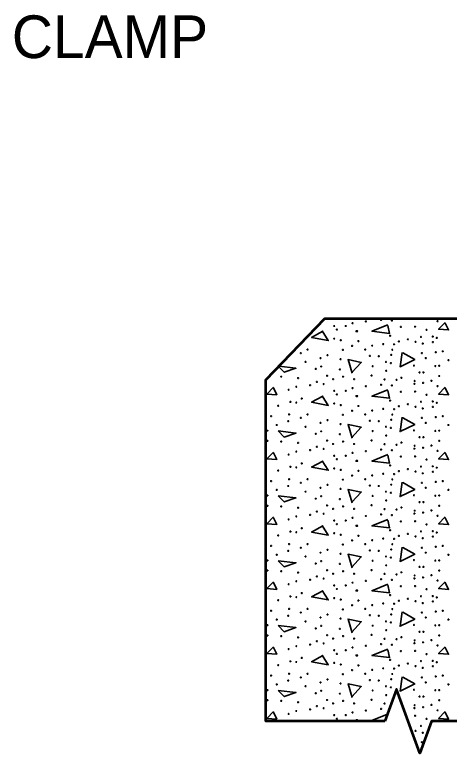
# Model space of a CAD drawing. Extents: x -105 to 751, y -65 to 479.
# Drawn here: x 328.8 to 359.4, y 310.5 to 362.5 of the extents above; entities that cross this region are included whole.
import ezdxf

# ---------------------------------------------------------------- set-up
doc = ezdxf.new("R2010")
doc.units = 0
doc.header["$LTSCALE"] = 1.2
doc.layers.add('1', color=7, linetype='Continuous', lineweight=35)

msp = doc.modelspace()

# ---------------------------------------------------------------- linework, layer by layer
at = {"layer": '1'}
for p, q in [((350.532, 312.839), (350.434, 312.786)), ((350.533, 312.786), (350.484, 312.863))]:
    msp.add_line(p, q, dxfattribs=at)
at = {"layer": '1', "lineweight": 53}
msp.add_lwpolyline([(354.913, 312.786), (346.512, 312.786), (346.512, 336.786), (350.68, 341.102), (385.481, 341.102), (389.649, 336.786), (389.649, 312.786), (381.249, 312.786), (380.428, 310.531), (378.786, 315.041), (377.965, 312.786), (358.196, 312.786), (357.375, 310.531), (355.733, 315.041)], close=True, dxfattribs=at)
at = {"layer": '1'}
for points in [[(355.116, 340.655), (353.988, 340.199), (355.236, 340.055), (355.116, 340.607)], [(359.148, 340.823), (358.692, 340.343), (359.388, 340.295), (359.148, 340.775)], [(350.532, 340.199), (349.74, 339.767), (350.916, 339.551), (350.484, 340.223)], [(356.172, 338.687), (357.012, 338.207), (355.98, 337.703), (356.124, 338.711)], [(352.596, 337.247), (352.308, 338.207), (353.244, 338.015), (352.572, 337.295)], [(347.439, 337.745), (348.636, 337.607), (347.82, 337.319), (347.417, 337.722)], [(347.052, 336.263), (346.596, 335.783), (347.292, 335.735), (347.052, 336.215)], [(355.116, 336.095), (353.988, 335.639), (355.236, 335.495), (355.116, 336.047)], [(359.148, 336.263), (358.692, 335.783), (359.388, 335.735), (359.148, 336.215)], [(350.532, 335.639), (349.74, 335.207), (350.916, 334.991), (350.484, 335.663)], [(356.172, 334.127), (357.012, 333.647), (355.98, 333.143), (356.124, 334.151)], [(352.596, 332.687), (352.308, 333.647), (353.244, 333.455), (352.572, 332.735)], [(347.052, 331.703), (346.596, 331.223), (347.292, 331.175), (347.052, 331.655)], [(355.116, 331.535), (353.988, 331.079), (355.236, 330.935), (355.116, 331.487)], [(359.148, 331.703), (358.692, 331.223), (359.388, 331.175), (359.148, 331.655)], [(350.532, 331.079), (349.74, 330.647), (350.916, 330.431), (350.484, 331.103)], [(356.172, 329.567), (357.012, 329.087), (355.98, 328.583), (356.124, 329.591)], [(352.596, 328.127), (352.308, 329.087), (353.244, 328.895), (352.572, 328.175)], [(347.052, 327.143), (346.596, 326.663), (347.292, 326.615), (347.052, 327.095)], [(355.116, 326.975), (353.988, 326.519), (355.236, 326.375), (355.116, 326.927)], [(359.148, 327.143), (358.692, 326.663), (359.388, 326.615), (359.148, 327.095)], [(350.532, 326.519), (349.74, 326.087), (350.916, 325.871), (350.484, 326.543)], [(356.172, 325.007), (357.012, 324.527), (355.98, 324.023), (356.124, 325.031)], [(352.596, 323.567), (352.308, 324.527), (353.244, 324.335), (352.572, 323.615)], [(347.052, 322.583), (346.596, 322.103), (347.292, 322.055), (347.052, 322.535)], [(359.148, 322.583), (358.692, 322.103), (359.388, 322.055), (359.148, 322.535)], [(350.532, 321.959), (349.74, 321.527), (350.916, 321.311), (350.484, 321.983)], [(355.116, 322.415), (353.988, 321.959), (355.236, 321.815), (355.116, 322.367)], [(356.172, 320.447), (357.012, 319.967), (355.98, 319.463), (356.124, 320.471)], [(352.596, 319.007), (352.308, 319.967), (353.244, 319.775), (352.572, 319.055)], [(347.052, 318.023), (346.596, 317.543), (347.292, 317.495), (347.052, 317.975)], [(355.116, 317.855), (353.988, 317.399), (355.236, 317.255), (355.116, 317.807)], [(359.148, 318.023), (358.692, 317.543), (359.388, 317.495), (359.148, 317.975)], [(350.532, 317.399), (349.74, 316.967), (350.916, 316.751), (350.484, 317.423)], [(356.172, 315.887), (357.012, 315.407), (355.98, 314.903), (356.124, 315.911)], [(352.596, 314.447), (352.308, 315.407), (353.244, 315.215), (352.572, 314.495)], [(347.052, 313.463), (346.596, 312.983), (347.292, 312.935), (347.052, 313.415)], [(355.095, 313.287), (353.988, 312.839), (354.45, 312.786)], [(359.148, 313.463), (358.692, 312.983), (359.388, 312.935), (359.148, 313.415)]]:
    msp.add_lwpolyline(points, dxfattribs=at)
for points in [[(347.388, 333.191), (348.636, 333.047), (347.82, 332.759)], [(347.388, 328.631), (348.636, 328.487), (347.82, 328.199)], [(347.388, 324.071), (348.636, 323.927), (347.82, 323.639)], [(347.388, 319.511), (348.636, 319.367), (347.82, 319.079)], [(347.388, 314.951), (348.636, 314.807), (347.82, 314.519)]]:
    msp.add_lwpolyline(points, close=True, dxfattribs=at)
for centre in [(352.629, 340.765), (353.568, 340.892), (354.633, 341.003), (355.397, 340.955), (356.987, 341.067), (358.618, 340.908), (351.341, 340.574), (351.532, 340.319), (352.152, 340.574), (352.9, 340.208), (352.963, 340.208), (356.033, 340.51), (357.035, 340.526), (357.846, 340.303), (351.341, 339.683), (355.269, 339.89), (356.526, 339.635), (357.448, 339.81), (358.275, 339.826), (358.555, 339.731), (351.802, 339.571), (352.598, 339.174), (353.043, 339.508), (354.013, 339.19), (354.792, 339.301), (355.556, 339.285), (355.89, 339.492), (357.067, 339.46), (357.576, 339.333), (358.291, 339.444), (348.987, 338.665), (349.465, 338.919), (351.946, 338.887), (353.52, 338.919), (355.349, 338.537), (355.429, 338.903), (357.512, 338.665), (358.482, 338.728), (358.984, 338.792), (349.321, 338.044), (350.371, 338.315), (350.864, 338.521), (351.787, 338.235), (353.854, 338.474), (354.474, 338.442), (354.983, 338.044), (357.782, 338.315), (359.382, 338.171), (350.037, 337.551), (350.419, 337.726), (351.739, 337.519), (354.045, 337.742), (355.333, 337.965), (356.955, 337.79), (358.458, 337.755), (358.73, 337.774), (347.604, 337.01), (350.832, 337.074), (351.961, 337.01), (353.965, 337.09), (354.999, 337.424), (357.353, 337.312), (357.623, 337.312), (358.73, 337.058), (348.797, 336.915), (350.117, 336.644), (350.594, 336.491), (351.262, 336.835), (352.741, 336.835), (354.888, 336.819), (355.731, 336.787), (356.065, 336.931), (356.987, 336.507), (357.003, 336.708), (357.591, 336.57), (358.18, 336.724), (348.129, 336.093), (348.669, 336.3), (349.64, 336.411), (351.341, 336.014), (352.152, 336.014), (352.629, 336.205), (353.568, 336.332), (354.633, 336.443), (355.397, 336.395), (356.033, 335.95), (357.035, 335.966), (358.618, 336.348), (349.051, 335.473), (351.532, 335.759), (352.9, 335.648), (352.963, 335.648), (357.846, 335.743), (347.397, 334.964), (348.256, 335.234), (348.669, 335.186), (351.341, 335.123), (351.802, 335.011), (353.043, 334.948), (355.269, 335.33), (355.89, 334.932), (356.526, 335.075), (357.448, 335.25), (358.275, 335.266), (358.555, 335.171), (352.598, 334.614), (354.013, 334.63), (354.792, 334.741), (355.556, 334.725), (357.067, 334.9), (357.576, 334.773), (358.291, 334.884), (346.888, 334.232), (348.097, 333.882), (348.16, 334.359), (348.987, 334.105), (349.465, 334.359), (350.864, 333.961), (351.946, 334.327), (353.52, 334.359), (353.854, 333.914), (354.474, 333.882), (355.349, 333.977), (355.429, 334.343), (357.512, 334.105), (358.482, 334.168), (358.984, 334.232), (347.286, 333.611), (349.321, 333.484), (350.371, 333.755), (351.787, 333.675), (354.983, 333.484), (355.333, 333.405), (357.782, 333.755), (359.382, 333.611), (346.634, 333.214), (350.037, 332.991), (350.419, 333.166), (351.739, 332.959), (354.045, 333.182), (354.999, 332.864), (356.955, 333.23), (358.458, 333.195), (358.73, 333.214), (346.634, 332.498), (347.604, 332.45), (348.797, 332.355), (350.832, 332.514), (351.961, 332.45), (353.965, 332.53), (356.065, 332.371), (357.353, 332.752), (357.623, 332.752), (358.73, 332.498), (349.64, 331.851), (350.117, 332.084), (350.594, 331.931), (351.262, 332.275), (352.741, 332.275), (354.633, 331.883), (354.888, 332.259), (355.397, 331.835), (355.731, 332.227), (356.987, 331.947), (357.003, 332.148), (357.591, 332.01), (358.18, 332.164), (358.618, 331.788), (348.129, 331.533), (348.669, 331.74), (351.341, 331.454), (352.152, 331.454), (352.629, 331.645), (353.568, 331.772), (356.033, 331.39), (357.035, 331.406), (349.051, 330.913), (351.532, 331.199), (352.9, 331.088), (352.963, 331.088), (355.269, 330.77), (357.846, 331.183), (347.397, 330.404), (348.256, 330.674), (348.669, 330.626), (351.341, 330.563), (351.802, 330.451), (353.043, 330.388), (355.89, 330.372), (356.526, 330.515), (357.067, 330.34), (357.448, 330.69), (358.275, 330.706), (358.291, 330.324), (358.555, 330.611), (348.16, 329.799), (349.465, 329.799), (351.946, 329.767), (352.598, 330.054), (353.52, 329.799), (354.013, 330.07), (354.792, 330.181), (355.429, 329.783), (355.556, 330.165), (357.576, 330.213), (346.888, 329.672), (348.097, 329.322), (348.987, 329.545), (350.371, 329.195), (350.864, 329.401), (353.854, 329.354), (354.474, 329.322), (355.349, 329.417), (357.512, 329.545), (357.782, 329.195), (358.482, 329.608), (358.984, 329.672), (347.286, 329.051), (349.321, 328.924), (351.787, 329.115), (354.983, 328.924), (355.333, 328.845), (359.382, 329.051), (346.634, 328.654), (350.037, 328.431), (350.419, 328.606), (351.739, 328.399), (354.045, 328.622), (354.999, 328.304), (356.955, 328.67), (357.353, 328.192), (357.623, 328.192), (358.458, 328.635), (358.73, 328.654), (346.634, 327.938), (347.604, 327.89), (348.797, 327.795), (350.832, 327.954), (351.262, 327.715), (351.961, 327.89), (352.741, 327.715), (353.965, 327.97), (354.888, 327.699), (355.731, 327.667), (356.065, 327.811), (358.73, 327.938), (348.669, 327.18), (349.64, 327.291), (350.117, 327.524), (350.594, 327.371), (353.568, 327.212), (354.633, 327.323), (355.397, 327.275), (356.987, 327.387), (357.003, 327.588), (357.591, 327.45), (358.18, 327.604), (358.618, 327.228), (348.129, 326.973), (351.341, 326.894), (351.532, 326.639), (352.152, 326.894), (352.629, 327.085), (356.033, 326.83), (357.035, 326.846), (357.846, 326.623), (348.256, 326.114), (349.051, 326.353), (352.9, 326.528), (352.963, 326.528), (355.269, 326.21), (357.448, 326.13), (358.275, 326.146), (347.397, 325.844), (348.669, 326.066), (351.341, 326.003), (351.802, 325.891), (353.043, 325.828), (354.792, 325.621), (355.556, 325.605), (355.89, 325.812), (356.526, 325.955), (357.067, 325.78), (357.576, 325.653), (358.291, 325.764), (358.555, 326.051), (346.888, 325.112), (348.16, 325.239), (349.465, 325.239), (351.946, 325.207), (352.598, 325.494), (353.52, 325.239), (354.013, 325.51), (355.429, 325.223), (358.482, 325.048), (358.984, 325.112), (348.097, 324.762), (348.987, 324.985), (350.371, 324.635), (350.864, 324.841), (351.787, 324.555), (353.854, 324.794), (354.474, 324.762), (355.349, 324.857), (357.512, 324.985), (357.782, 324.635), (346.634, 324.094), (347.286, 324.491), (349.321, 324.364), (350.419, 324.046), (354.045, 324.062), (354.983, 324.364), (355.333, 324.285), (356.955, 324.11), (358.458, 324.075), (358.73, 324.094), (359.382, 324.491), (350.037, 323.871), (351.739, 323.839), (354.999, 323.744), (357.353, 323.632), (357.623, 323.632), (346.634, 323.378), (347.604, 323.33), (348.797, 323.235), (350.117, 322.964), (350.832, 323.394), (351.262, 323.155), (351.961, 323.33), (352.741, 323.155), (353.965, 323.41), (354.888, 323.139), (355.731, 323.107), (356.065, 323.251), (357.003, 323.028), (358.18, 323.044), (358.73, 323.378), (348.669, 322.62), (349.64, 322.731), (350.594, 322.811), (352.629, 322.525), (353.568, 322.652), (354.633, 322.763), (355.397, 322.715), (356.987, 322.827), (357.591, 322.89), (358.618, 322.668), (348.129, 322.413), (351.341, 322.334), (351.532, 322.079), (352.152, 322.334), (352.9, 321.968), (352.963, 321.968), (356.033, 322.27), (357.035, 322.286), (357.846, 322.063), (348.256, 321.554), (348.669, 321.506), (349.051, 321.793), (351.341, 321.443), (355.269, 321.65), (357.448, 321.57), (358.275, 321.586), (358.555, 321.491), (347.397, 321.284), (351.802, 321.331), (352.598, 320.934), (353.043, 321.268), (354.013, 320.95), (354.792, 321.061), (355.556, 321.045), (355.89, 321.252), (356.526, 321.395), (357.067, 321.22), (357.576, 321.093), (358.291, 321.204), (346.888, 320.552), (348.16, 320.679), (348.987, 320.425), (349.465, 320.679), (351.946, 320.647), (353.52, 320.679), (355.429, 320.663), (357.512, 320.425), (358.482, 320.488), (358.984, 320.552), (347.286, 319.931), (348.097, 320.202), (350.371, 320.075), (350.864, 320.281), (351.787, 319.995), (353.854, 320.234), (354.474, 320.202), (355.349, 320.297), (357.782, 320.075), (359.382, 319.931), (346.634, 319.534), (349.321, 319.804), (350.419, 319.486), (354.045, 319.502), (354.983, 319.804), (355.333, 319.725), (356.955, 319.55), (358.458, 319.515), (358.73, 319.534), (346.634, 318.818), (350.037, 319.311), (350.832, 318.834), (351.739, 319.279), (353.965, 318.85), (354.999, 319.184), (357.353, 319.072), (357.623, 319.072), (358.73, 318.818), (347.604, 318.77), (348.797, 318.675), (350.117, 318.404), (351.262, 318.595), (351.961, 318.77), (352.741, 318.595), (354.888, 318.579), (355.731, 318.547), (356.065, 318.691), (357.003, 318.468), (357.591, 318.33), (358.18, 318.484), (348.129, 317.853), (348.669, 318.06), (349.64, 318.171), (350.594, 318.251), (351.341, 317.774), (352.152, 317.774), (352.629, 317.965), (353.568, 318.092), (354.633, 318.203), (355.397, 318.155), (356.987, 318.267), (358.618, 318.108), (351.532, 317.519), (352.9, 317.408), (352.963, 317.408), (356.033, 317.71), (357.035, 317.726), (357.846, 317.503), (348.256, 316.994), (348.669, 316.946), (349.051, 317.233), (351.341, 316.883), (351.802, 316.771), (355.269, 317.09), (356.526, 316.835), (357.448, 317.01), (358.275, 317.026), (358.555, 316.931), (347.397, 316.724), (352.598, 316.374), (353.043, 316.708), (354.013, 316.39), (354.792, 316.501), (355.556, 316.485), (355.89, 316.692), (357.067, 316.66), (357.576, 316.533), (358.291, 316.644), (346.888, 315.992), (348.16, 316.119), (348.987, 315.865), (349.465, 316.119), (350.864, 315.721), (351.946, 316.087), (353.52, 316.119), (355.349, 315.737), (355.429, 316.103), (357.512, 315.865), (358.482, 315.928), (358.984, 315.992), (347.286, 315.371), (348.097, 315.642), (349.321, 315.244), (350.371, 315.515), (351.787, 315.435), (353.854, 315.674), (354.474, 315.642), (354.983, 315.244), (357.782, 315.515), (359.382, 315.371), (346.634, 314.974), (350.037, 314.751), (350.419, 314.926), (351.739, 314.719), (354.045, 314.942), (355.333, 315.165), (356.955, 314.99), (358.458, 314.955), (358.73, 314.974), (346.634, 314.258), (347.604, 314.21), (350.832, 314.274), (351.961, 314.21), (353.965, 314.29), (354.999, 314.624), (357.353, 314.512), (357.623, 314.512), (358.73, 314.258), (348.797, 314.115), (350.117, 313.844), (350.594, 313.691), (351.262, 314.035), (352.741, 314.035), (354.633, 313.643), (354.888, 314.019), (356.987, 313.707), (357.003, 313.908), (357.591, 313.77), (358.18, 313.924), (348.129, 313.293), (348.669, 313.5), (349.64, 313.611), (351.341, 313.214), (352.152, 313.214), (352.629, 313.405), (353.568, 313.532), (357.035, 313.166), (358.618, 313.548), (351.532, 312.959), (352.9, 312.848), (352.963, 312.848), (357.846, 312.943), (357.067, 312.1), (357.448, 312.45), (357.576, 311.973), (357.512, 311.305)]:
    msp.add_circle(centre, 0.0318, dxfattribs=at)
for centre, start, end in [((350.594, 341.051), 284.1898, 347.809), ((357.591, 341.13), 243.9794, 296.0206), ((348.097, 338.442), 245.5706, 26.4282), ((346.522, 336.348), 251.7798, 108.2202), ((346.522, 331.788), 251.7798, 108.2202), ((346.522, 327.228), 251.7798, 108.2202), ((346.522, 322.668), 251.7798, 108.2202), ((346.522, 318.108), 251.7798, 108.2202), ((356.065, 314.131), 290.0896, 109.9084), ((346.522, 313.548), 251.7798, 108.2202)]:
    msp.add_arc(centre, 0.0318, start, end, dxfattribs=at)

# ---------------------------------------------------------------- texts
msp.add_text('CLAMP', height=3, dxfattribs=at).set_placement((328.638, 359.414))

doc.saveas('drawing.dxf')
